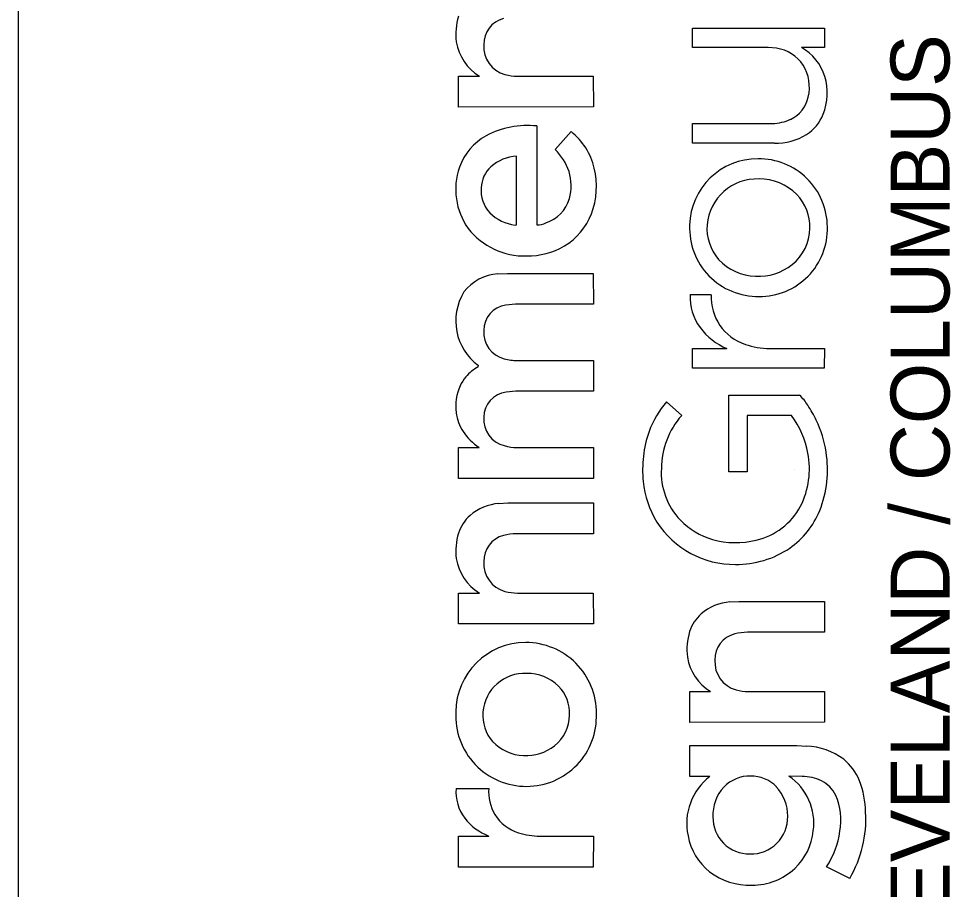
# Model space of a CAD drawing. Extents: x -0.3 to 34, y 0 to 22.
# Drawn here: x 32 to 32.901, y 3.094 to 3.936 of the extents above; entities that cross this region are included whole.
import ezdxf

# ---------------------------------------------------------------- set-up
doc = ezdxf.new("R2010")
doc.units = 0
doc.layers.add('SH_Border', color=7, linetype='Continuous')
doc.layers.add('SH_Data', color=7, linetype='Continuous')

msp = doc.modelspace()

# ---------------------------------------------------------------- linework, layer by layer
at = {"layer": 'SH_Border'}
msp.add_line((32, 0.5), (32, 21.5), dxfattribs=at)
at = {"layer": 'SH_Data'}
for p, q in [((32.65152, 3.90801), (32.65153, 3.92672)), ((32.65153, 3.92672), (32.7791, 3.92664)), ((32.7791, 3.92664), (32.77908, 3.90796)), ((32.7249, 3.90796), (32.65152, 3.90801)), ((32.7328, 3.90727), (32.7249, 3.90796)), ((32.77908, 3.90796), (32.75689, 3.90796)), ((32.42542, 3.88016), (32.44552, 3.88021)), ((32.42542, 3.85035), (32.42542, 3.88016)), ((32.48222, 3.88021), (32.55569, 3.88021)), ((32.55569, 3.88021), (32.55571, 3.85045)), ((32.55571, 3.85045), (32.42542, 3.85035)), ((32.50108, 3.83209), (32.50118, 3.73657)), ((32.65154, 3.83443), (32.72905, 3.8345)), ((32.65165, 3.81543), (32.65154, 3.83443)), ((32.51882, 3.80927), (32.53422, 3.82662)), ((32.73073, 3.81543), (32.65165, 3.81543)), ((32.48144, 3.73644), (32.48144, 3.80296)), ((32.48016, 3.73628), (32.48144, 3.73644)), ((32.46329, 3.68915), (32.47259, 3.68968)), ((32.47259, 3.68968), (32.55557, 3.68968)), ((32.55557, 3.68968), (32.55571, 3.65982)), ((32.64932, 3.66907), (32.66978, 3.66907)), ((32.48058, 3.65981), (32.47102, 3.65881)), ((32.55571, 3.65982), (32.48058, 3.65981)), ((32.65152, 3.61699), (32.68476, 3.617)), ((32.65152, 3.598), (32.65152, 3.61699)), ((32.72605, 3.61703), (32.7791, 3.61696)), ((32.7791, 3.61696), (32.77903, 3.598)), ((32.48218, 3.60553), (32.55571, 3.60548)), ((32.55571, 3.60548), (32.55571, 3.57568)), ((32.44443, 3.59922), (32.44455, 3.60072)), ((32.77903, 3.598), (32.65152, 3.598)), ((32.4809, 3.57567), (32.47143, 3.57474)), ((32.55571, 3.57568), (32.4809, 3.57567)), ((32.6868, 3.57185), (32.75516, 3.57192)), ((32.6868, 3.49778), (32.6868, 3.57185)), ((32.62636, 3.56548), (32.64114, 3.55241)), ((32.70448, 3.55241), (32.70432, 3.49775)), ((32.74737, 3.55227), (32.70448, 3.55241)), ((32.42542, 3.49152), (32.42545, 3.52138)), ((32.42545, 3.52138), (32.44515, 3.52138)), ((32.48206, 3.52138), (32.55571, 3.52136)), ((32.55571, 3.52136), (32.55571, 3.49156)), ((32.70432, 3.49775), (32.6868, 3.49778)), ((32.75, 3.5), (32.75, 3.5)), ((32.55571, 3.49156), (32.42542, 3.49152)), ((32.46439, 3.46736), (32.47289, 3.46783)), ((32.47289, 3.46783), (32.55571, 3.46783)), ((32.55571, 3.46783), (32.55571, 3.43804)), ((32.55571, 3.43804), (32.4814, 3.43796)), ((32.42542, 3.38066), (32.44552, 3.38071)), ((32.42542, 3.35086), (32.42542, 3.38066)), ((32.48222, 3.38071), (32.55569, 3.38071)), ((32.55569, 3.38071), (32.55571, 3.35096)), ((32.68784, 3.3722), (32.69634, 3.37266)), ((32.69634, 3.37266), (32.77916, 3.37266)), ((32.77916, 3.37266), (32.77917, 3.34287)), ((32.55571, 3.35096), (32.42542, 3.35086)), ((32.77917, 3.34287), (32.70485, 3.3428)), ((32.64888, 3.2855), (32.66897, 3.28555)), ((32.64888, 3.25569), (32.64888, 3.2855)), ((32.70568, 3.28555), (32.77915, 3.28555)), ((32.77915, 3.28555), (32.77917, 3.25579)), ((32.77917, 3.25579), (32.64888, 3.25569)), ((32.6489, 3.20336), (32.64889, 3.23322)), ((32.64889, 3.23322), (32.75236, 3.23322)), ((32.75236, 3.23322), (32.76191, 3.23285)), ((32.66836, 3.20336), (32.6489, 3.20336)), ((32.75763, 3.20356), (32.74487, 3.20361)), ((32.42299, 3.19193), (32.45454, 3.19193)), ((32.42542, 3.14577), (32.45473, 3.14579)), ((32.42542, 3.11593), (32.42542, 3.14577)), ((32.50413, 3.14581), (32.55571, 3.14573)), ((32.55571, 3.14573), (32.55565, 3.11593)), ((32.55565, 3.11593), (32.42542, 3.11593)), ((32.8036, 3.10491), (32.7812, 3.11598))]:
    msp.add_line(p, q, dxfattribs=at)
for points in [[(32.7328, 3.90727), (32.7249, 3.90796), (32.65152, 3.90801), (32.65153, 3.92672), (32.7791, 3.92664), (32.77908, 3.90796), (32.75689, 3.90796)], [(32.42542, 3.85035), (32.42542, 3.88016), (32.44552, 3.88021)], [(32.48222, 3.88021), (32.55569, 3.88021), (32.55571, 3.85045), (32.42542, 3.85035)], [(32.50108, 3.83209), (32.50118, 3.73657)], [(32.73073, 3.81543), (32.65165, 3.81543), (32.65154, 3.83443), (32.72905, 3.8345)], [(32.51882, 3.80927), (32.53422, 3.82662)], [(32.48016, 3.73628), (32.48144, 3.73644), (32.48144, 3.80296)], [(32.46329, 3.68915), (32.47259, 3.68968), (32.55557, 3.68968), (32.55571, 3.65982), (32.48058, 3.65981), (32.47102, 3.65881)], [(32.64932, 3.66907), (32.66978, 3.66907)], [(32.72605, 3.61703), (32.7791, 3.61696), (32.77903, 3.598), (32.65152, 3.598)], [(32.65152, 3.598), (32.65152, 3.61699), (32.68476, 3.617)], [(32.48218, 3.60553), (32.55571, 3.60548), (32.55571, 3.57568), (32.4809, 3.57567), (32.47143, 3.57474)], [(32.44443, 3.59922), (32.44455, 3.60072)], [(32.74737, 3.55227), (32.70448, 3.55241), (32.70432, 3.49775), (32.6868, 3.49778), (32.6868, 3.57185), (32.75516, 3.57192)], [(32.62636, 3.56548), (32.64114, 3.55241)], [(32.42542, 3.49152), (32.42545, 3.52138), (32.44515, 3.52138)], [(32.48206, 3.52138), (32.55571, 3.52136), (32.55571, 3.49156), (32.42542, 3.49152)], [(32.46439, 3.46736), (32.47289, 3.46783), (32.55571, 3.46783), (32.55571, 3.43804), (32.4814, 3.43796)], [(32.42542, 3.35086), (32.42542, 3.38066), (32.44552, 3.38071)], [(32.48222, 3.38071), (32.55569, 3.38071), (32.55571, 3.35096), (32.42542, 3.35086)], [(32.68784, 3.3722), (32.69634, 3.37266), (32.77916, 3.37266), (32.77917, 3.34287), (32.70485, 3.3428)], [(32.64888, 3.25569), (32.64888, 3.2855), (32.66897, 3.28555)], [(32.70568, 3.28555), (32.77915, 3.28555), (32.77917, 3.25579), (32.64888, 3.25569)], [(32.66836, 3.20336), (32.6489, 3.20336), (32.64889, 3.23322), (32.75236, 3.23322), (32.76191, 3.23285)], [(32.75763, 3.20356), (32.74487, 3.20361)], [(32.42299, 3.19193), (32.45454, 3.19193)], [(32.50413, 3.14581), (32.55571, 3.14573), (32.55565, 3.11593), (32.42542, 3.11593)], [(32.42542, 3.11593), (32.42542, 3.14577), (32.45473, 3.14579)], [(32.8036, 3.10491), (32.7812, 3.11598)]]:
    msp.add_lwpolyline(points, dxfattribs=at)
for centre, radius, start, end in [((32.47872, 3.92108), 0.05602, 162.27398, 187.79173), ((32.47872, 3.92108), 0.05602, 162.27398, 187.79173), ((32.47482, 3.91155), 0.02498, 103.68683, 182.21395), ((32.47482, 3.91155), 0.02498, 103.68683, 182.21395), ((32.47027, 3.9209), 0.04763, 188.96462, 238.69865), ((32.47027, 3.9209), 0.04763, 188.96462, 238.69865), ((32.47735, 3.90846), 0.02757, 175.58441, 255.13816), ((32.47735, 3.90846), 0.02757, 175.58441, 255.13816), ((32.72711, 3.86998), 0.03772, 33.50082, 81.32954), ((32.72711, 3.86998), 0.03772, 33.50082, 81.32954), ((32.73239, 3.86485), 0.04959, 17.62209, 60.38974), ((32.73239, 3.86485), 0.04959, 17.62209, 60.38974), ((32.72414, 3.8695), 0.04048, 346.56179, 31.75389), ((32.72414, 3.8695), 0.04048, 346.56179, 31.75389), ((32.48183, 3.92235), 0.04215, 254.08913, 270.52838), ((32.48183, 3.92235), 0.04215, 254.08913, 270.52838), ((32.72343, 3.86415), 0.05838, 339.16197, 15.61485), ((32.72343, 3.86415), 0.05838, 339.16197, 15.61485), ((32.73371, 3.86616), 0.03042, 294.63214, 348.48625), ((32.73371, 3.86616), 0.03042, 294.63214, 348.48625), ((32.72747, 3.88081), 0.04633, 271.95199, 294.08943), ((32.72747, 3.88081), 0.04633, 271.95199, 294.08943), ((32.739, 3.85901), 0.04201, 303.10391, 338.15613), ((32.739, 3.85901), 0.04201, 303.10391, 338.15613), ((32.49176, 3.74874), 0.08387, 83.62118, 118.28448), ((32.49176, 3.74874), 0.08387, 83.62118, 118.28448), ((32.47894, 3.77368), 0.05583, 118.82935, 160.62242), ((32.47894, 3.77368), 0.05583, 118.82935, 160.62242), ((32.49399, 3.7763), 0.06443, 13.53275, 51.36266), ((32.49399, 3.7763), 0.06443, 13.53275, 51.36266), ((32.7321, 3.87256), 0.05715, 268.62699, 301.47779), ((32.7321, 3.87256), 0.05715, 268.62699, 301.47779), ((32.4844, 3.76071), 0.04236, 94.01311, 130.88062), ((32.4844, 3.76071), 0.04236, 94.01311, 130.88062), ((32.48033, 3.77018), 0.05485, 19.0387, 45.44322), ((32.48033, 3.77018), 0.05485, 19.0387, 45.44322), ((32.71435, 3.73484), 0.06552, 89.48213, 178.77752), ((32.71435, 3.73484), 0.06552, 89.48213, 178.77752), ((32.71582, 3.73414), 0.06623, 0.42265, 90.7613), ((32.71582, 3.73414), 0.06623, 0.42265, 90.7613), ((32.48697, 3.77074), 0.06438, 160.52138, 215.78155), ((32.48697, 3.77074), 0.06438, 160.52138, 215.78155), ((32.47703, 3.7709), 0.02985, 132.98553, 177.1802), ((32.47703, 3.7709), 0.02985, 132.98553, 177.1802), ((32.48724, 3.77433), 0.04701, 344.60723, 17.00675), ((32.48724, 3.77433), 0.04701, 344.60723, 17.00675), ((32.48289, 3.77384), 0.0758, 339.35431, 13.37708), ((32.48289, 3.77384), 0.0758, 339.35431, 13.37708), ((32.71397, 3.73244), 0.04846, 87.68827, 175.01696), ((32.71397, 3.73244), 0.04846, 87.68827, 175.01696), ((32.71659, 3.73036), 0.05052, 44.91202, 90.75914), ((32.71659, 3.73036), 0.05052, 44.91202, 90.75914), ((32.47824, 3.76966), 0.03114, 175.00138, 223.2876), ((32.47824, 3.76966), 0.03114, 175.00138, 223.2876), ((32.71955, 3.73452), 0.04549, 358.32279, 43.83486), ((32.71955, 3.73452), 0.04549, 358.32279, 43.83486), ((32.49895, 3.77177), 0.03504, 288.01084, 343.55364), ((32.49895, 3.77177), 0.03504, 288.01084, 343.55364), ((32.48546, 3.77826), 0.04232, 225.06454, 262.79701), ((32.48546, 3.77826), 0.04232, 225.06454, 262.79701), ((32.49548, 3.76982), 0.0626, 300.94393, 338.73223), ((32.49548, 3.76982), 0.0626, 300.94393, 338.73223), ((32.48908, 3.77516), 0.06872, 217.74341, 271.65606), ((32.48908, 3.77516), 0.06872, 217.74341, 271.65606), ((32.50129, 3.75678), 0.02021, 269.70042, 294.87295), ((32.50129, 3.75678), 0.02021, 269.70042, 294.87295), ((32.71483, 3.7334), 0.06606, 177.53728, 270.94524), ((32.71483, 3.7334), 0.06606, 177.53728, 270.94524), ((32.71085, 3.73311), 0.0453, 175.51467, 221.42047), ((32.71085, 3.73311), 0.0453, 175.51467, 221.42047), ((32.71671, 3.73271), 0.06536, 269.30834, 1.67905), ((32.71671, 3.73271), 0.06536, 269.30834, 1.67905), ((32.71931, 3.73374), 0.04572, 308.90382, 359.30947), ((32.71931, 3.73374), 0.04572, 308.90382, 359.30947), ((32.49204, 3.77702), 0.07055, 269.20529, 300.33566), ((32.49204, 3.77702), 0.07055, 269.20529, 300.33566), ((32.71399, 3.73734), 0.05046, 222.66255, 268.37331), ((32.71399, 3.73734), 0.05046, 222.66255, 268.37331), ((32.71567, 3.73859), 0.05178, 266.55312, 308.67253), ((32.71567, 3.73859), 0.05178, 266.55312, 308.67253), ((32.46638, 3.64404), 0.04521, 93.91118, 142.30723), ((32.46638, 3.64404), 0.04521, 93.91118, 142.30723), ((32.47585, 3.64373), 0.05319, 148.28793, 233.9556), ((32.47585, 3.64373), 0.05319, 148.28793, 233.9556), ((32.69878, 3.66662), 0.04952, 177.16211, 216.28024), ((32.69878, 3.66662), 0.04952, 177.16211, 216.28024), ((32.71735, 3.66638), 0.04764, 176.76988, 252.15044), ((32.71735, 3.66638), 0.04764, 176.76988, 252.15044), ((32.47384, 3.63499), 0.02399, 96.75763, 181.6251), ((32.47384, 3.63499), 0.02399, 96.75763, 181.6251), ((32.47577, 3.63241), 0.02597, 175.81573, 256.16716), ((32.47577, 3.63241), 0.02597, 175.81573, 256.16716), ((32.70975, 3.67555), 0.06366, 216.91526, 246.88619), ((32.70975, 3.67555), 0.06366, 216.91526, 246.88619), ((32.7269, 3.69175), 0.07473, 251.13884, 269.34694), ((32.7269, 3.69175), 0.07473, 251.13884, 269.34694), ((32.4817, 3.65053), 0.04501, 254.34629, 270.61033), ((32.4817, 3.65053), 0.04501, 254.34629, 270.61033), ((32.4638, 3.56267), 0.04137, 117.91625, 139.24296), ((32.4638, 3.56267), 0.04137, 117.91625, 139.24296), ((32.46194, 3.56452), 0.03875, 139.52447, 154.84698), ((32.46194, 3.56452), 0.03875, 139.52447, 154.84698), ((32.47144, 3.5612), 0.04877, 156.06382, 187.3493), ((32.47144, 3.5612), 0.04877, 156.06382, 187.3493), ((32.47421, 3.55056), 0.02434, 96.5532, 179.94902), ((32.47421, 3.55056), 0.02434, 96.5532, 179.94902), ((32.72498, 3.53937), 0.04438, 30.98913, 47.16099), ((32.72498, 3.53937), 0.04438, 30.98913, 47.16099), ((32.70163, 3.50187), 0.09855, 139.79476, 159.13696), ((32.70163, 3.50187), 0.09855, 139.79476, 159.13696), ((32.67091, 3.50018), 0.11106, 25.30315, 33.96179), ((32.67091, 3.50018), 0.11106, 25.30315, 33.96179), ((32.46461, 3.55974), 0.04181, 186.5579, 213.38846), ((32.46461, 3.55974), 0.04181, 186.5579, 213.38846), ((32.47608, 3.54863), 0.02628, 175.722, 255.78627), ((32.47608, 3.54863), 0.02628, 175.722, 255.78627), ((32.69899, 3.50079), 0.07753, 138.25804, 179.70064), ((32.69899, 3.50079), 0.07753, 138.25804, 179.70064), ((32.67889, 3.50099), 0.08556, 10.07509, 36.83189), ((32.67889, 3.50099), 0.08556, 10.07509, 36.83189), ((32.6704, 3.49987), 0.11166, 8.80339, 25.33484), ((32.6704, 3.49987), 0.11166, 8.80339, 25.33484), ((32.47886, 3.57078), 0.0598, 214.70433, 235.68724), ((32.47886, 3.57078), 0.0598, 214.70433, 235.68724), ((32.7187, 3.49968), 0.11536, 161.14379, 185.62812), ((32.7187, 3.49968), 0.11536, 161.14379, 185.62812), ((32.48195, 3.56518), 0.0438, 253.66719, 270.14979), ((32.48195, 3.56518), 0.0438, 253.66719, 270.14979), ((32.68425, 3.50057), 0.08036, 333.46689, 11.03668), ((32.68425, 3.50057), 0.08036, 333.46689, 11.03668), ((32.67564, 3.49977), 0.10649, 338.28866, 9.28548), ((32.67564, 3.49977), 0.10649, 338.28866, 9.28548), ((32.68811, 3.49732), 0.06676, 176.66577, 223.6912), ((32.68811, 3.49732), 0.06676, 176.66577, 223.6912), ((32.69336, 3.49699), 0.08987, 185.50773, 212.01294), ((32.69336, 3.49699), 0.08987, 185.50773, 212.01294), ((32.46871, 3.41767), 0.04988, 94.97056, 130.22484), ((32.46871, 3.41767), 0.04988, 94.97056, 130.22484), ((32.69868, 3.49547), 0.0652, 282.88151, 331.81475), ((32.69868, 3.49547), 0.0652, 282.88151, 331.81475), ((32.69835, 3.49168), 0.08241, 305.03061, 337.67573), ((32.69835, 3.49168), 0.08241, 305.03061, 337.67573), ((32.46348, 3.42602), 0.04016, 132.22383, 161.68229), ((32.46348, 3.42602), 0.04016, 132.22383, 161.68229), ((32.69045, 3.50011), 0.07039, 224.02147, 253.88), ((32.69045, 3.50011), 0.07039, 224.02147, 253.88), ((32.69211, 3.49748), 0.08908, 212.70222, 270.71399), ((32.69211, 3.49748), 0.08908, 212.70222, 270.71399), ((32.47872, 3.42158), 0.05602, 162.27398, 187.79173), ((32.47872, 3.42158), 0.05602, 162.27398, 187.79173), ((32.47482, 3.41206), 0.02498, 103.68683, 182.21395), ((32.47482, 3.41206), 0.02498, 103.68683, 182.21395), ((32.48108, 3.39196), 0.04601, 89.60515, 105.33026), ((32.48108, 3.39196), 0.04601, 89.60515, 105.33026), ((32.69318, 3.51254), 0.08309, 254.45353, 283.9512), ((32.69318, 3.51254), 0.08309, 254.45353, 283.9512), ((32.69429, 3.49979), 0.09138, 269.3273, 304.19632), ((32.69429, 3.49979), 0.09138, 269.3273, 304.19632), ((32.47027, 3.42141), 0.04763, 188.96462, 238.69865), ((32.47027, 3.42141), 0.04763, 188.96462, 238.69865), ((32.47735, 3.40897), 0.02757, 175.58441, 255.13816), ((32.47735, 3.40897), 0.02757, 175.58441, 255.13816), ((32.48183, 3.42286), 0.04215, 254.08913, 270.52838), ((32.48183, 3.42286), 0.04215, 254.08913, 270.52838), ((32.69216, 3.32251), 0.04988, 94.97056, 130.22484), ((32.69216, 3.32251), 0.04988, 94.97056, 130.22484), ((32.68694, 3.33085), 0.04016, 132.22383, 161.68229), ((32.68694, 3.33085), 0.04016, 132.22383, 161.68229), ((32.70217, 3.32642), 0.05602, 162.27398, 187.79173), ((32.70217, 3.32642), 0.05602, 162.27398, 187.79173), ((32.70453, 3.29679), 0.04601, 89.60515, 105.33026), ((32.70453, 3.29679), 0.04601, 89.60515, 105.33026), ((32.69828, 3.31689), 0.02498, 103.68683, 182.21395), ((32.69828, 3.31689), 0.02498, 103.68683, 182.21395), ((32.49014, 3.26543), 0.0674, 89.84756, 179.64047), ((32.49014, 3.26543), 0.0674, 89.84756, 179.64047), ((32.49057, 3.26474), 0.0681, 359.54009, 90.21138), ((32.49057, 3.26474), 0.0681, 359.54009, 90.21138), ((32.69372, 3.32624), 0.04763, 188.96462, 238.69865), ((32.69372, 3.32624), 0.04763, 188.96462, 238.69865), ((32.7008, 3.31381), 0.02757, 175.58441, 255.13816), ((32.7008, 3.31381), 0.02757, 175.58441, 255.13816), ((32.48923, 3.26263), 0.0404, 87.04809, 175.57259), ((32.48923, 3.26263), 0.0404, 87.04809, 175.57259), ((32.49204, 3.25999), 0.04299, 45.84264, 90.98008), ((32.49204, 3.25999), 0.04299, 45.84264, 90.98008), ((32.49458, 3.26421), 0.03821, 357.88569, 44.15902), ((32.49458, 3.26421), 0.03821, 357.88569, 44.15902), ((32.70529, 3.32769), 0.04215, 254.08913, 270.52838), ((32.70529, 3.32769), 0.04215, 254.08913, 270.52838), ((32.49083, 3.26209), 0.06819, 176.8344, 270.40384), ((32.49083, 3.26209), 0.06819, 176.8344, 270.40384), ((32.48729, 3.2625), 0.03848, 175.15378, 221.14706), ((32.48729, 3.2625), 0.03848, 175.15378, 221.14706), ((32.49123, 3.26139), 0.06749, 270.06243, 2.37759), ((32.49123, 3.26139), 0.06749, 270.06243, 2.37759), ((32.49446, 3.26318), 0.0383, 308.28936, 359.43468), ((32.49446, 3.26318), 0.0383, 308.28936, 359.43468), ((32.48919, 3.26607), 0.04228, 223.09994, 268.80895), ((32.48919, 3.26607), 0.04228, 223.09994, 268.80895), ((32.49096, 3.2679), 0.04418, 266.56515, 308.06078), ((32.49096, 3.2679), 0.04418, 266.56515, 308.06078), ((32.75907, 3.16789), 0.06503, 53.40344, 87.49062), ((32.75907, 3.16789), 0.06503, 53.40344, 87.49062), ((32.76517, 3.18039), 0.05141, 21.60748, 50.5577), ((32.76517, 3.18039), 0.05141, 21.60748, 50.5577), ((32.70292, 3.15813), 0.05692, 127.37482, 192.22468), ((32.70292, 3.15813), 0.05692, 127.37482, 192.22468), ((32.70693, 3.16927), 0.0346, 88.47302, 136.42562), ((32.70693, 3.16927), 0.0346, 88.47302, 136.42562), ((32.70814, 3.16963), 0.03424, 44.27195, 90.47623), ((32.70814, 3.16963), 0.03424, 44.27195, 90.47623), ((32.71421, 3.15829), 0.05472, 352.1125, 55.92295), ((32.71421, 3.15829), 0.05472, 352.1125, 55.92295), ((32.75666, 3.15725), 0.04633, 65.01687, 88.8011), ((32.75666, 3.15725), 0.04633, 65.01687, 88.8011), ((32.7626, 3.17155), 0.03085, 26.26808, 63.80301), ((32.7626, 3.17155), 0.03085, 26.26808, 63.80301), ((32.73069, 3.16714), 0.08835, 1.15143, 21.3627), ((32.73069, 3.16714), 0.08835, 1.15143, 21.3627), ((32.46616, 3.18882), 0.04329, 175.87313, 216.34747), ((32.46616, 3.18882), 0.04329, 175.87313, 216.34747), ((32.50087, 3.18948), 0.04639, 176.9688, 209.60636), ((32.50087, 3.18948), 0.04639, 176.9688, 209.60636), ((32.71141, 3.16602), 0.0401, 137.46739, 182.33237), ((32.71141, 3.16602), 0.0401, 137.46739, 182.33237), ((32.70368, 3.166), 0.03996, 358.57141, 43.53765), ((32.70368, 3.166), 0.03996, 358.57141, 43.53765), ((32.73565, 3.16154), 0.05953, 349.30734, 23.43071), ((32.73565, 3.16154), 0.05953, 349.30734, 23.43071), ((32.47466, 3.19716), 0.05511, 218.09809, 248.7907), ((32.47466, 3.19716), 0.05511, 218.09809, 248.7907), ((32.49514, 3.18814), 0.04079, 211.94466, 253.2028), ((32.49514, 3.18814), 0.04079, 211.94466, 253.2028), ((32.70645, 3.1637), 0.03511, 178.88208, 271.08374), ((32.70645, 3.1637), 0.03511, 178.88208, 271.08374), ((32.70818, 3.16404), 0.03546, 268.27882, 1.55016), ((32.70818, 3.16404), 0.03546, 268.27882, 1.55016), ((32.70538, 3.16244), 0.11383, 329.6388, 3.25998), ((32.70538, 3.16244), 0.11383, 329.6388, 3.25998), ((32.50465, 3.2165), 0.07069, 252.46555, 269.57296), ((32.50465, 3.2165), 0.07069, 252.46555, 269.57296), ((32.70463, 3.15696), 0.05837, 190.75182, 231.28919), ((32.70463, 3.15696), 0.05837, 190.75182, 231.28919), ((32.70988, 3.15708), 0.05887, 313.74196, 353.8554), ((32.70988, 3.15708), 0.05887, 313.74196, 353.8554), ((32.70738, 3.16334), 0.08771, 327.31495, 351.57478), ((32.70738, 3.16334), 0.08771, 327.31495, 351.57478), ((32.70632, 3.16112), 0.06269, 232.46061, 272.59022), ((32.70632, 3.16112), 0.06269, 232.46061, 272.59022), ((32.70954, 3.15901), 0.06051, 269.6361, 312.70877), ((32.70954, 3.15901), 0.06051, 269.6361, 312.70877)]:
    msp.add_arc(centre, radius, start, end, dxfattribs=at)

# ---------------------------------------------------------------- texts
msp.add_text('AKRON / CLEVELAND / COLUMBUS', height=0.056969, rotation=90, dxfattribs=at).set_placement((32.90012, 2.638))

doc.saveas('drawing.dxf')
